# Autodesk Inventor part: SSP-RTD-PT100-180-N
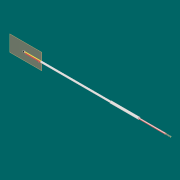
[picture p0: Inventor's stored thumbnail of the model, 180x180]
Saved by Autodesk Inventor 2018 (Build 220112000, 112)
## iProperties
Created: 2017-06
Part Number: SSP-RTD-PT100-180-N
Material: Generic
Document SubType Name: Modeling
Designer: JN
Density: 1 g/cm^3
Appearance: Smooth - Black
Author: JN
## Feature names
1. Extrusion1
2. Extrusion2
3. Extrusion3
4. Extrusion7
5. Extrusion8
6. Sweep1
7. Extrusion10
8. Loft8
9. Loft9
10. Loft10
11. Extrusion11
12. Extrusion12
13. Sweep5
14. Extrusion15
## Parameters: d0 = 50.8 mm, d1 = 25.4 mm, d2 = 0.0889 mm, d3 = 0, d4 = 2.54 mm, d5 = 2.286 mm, d6 = 2.032 mm, d7 = 1.016 mm, d8 = 0, d9 = 0.508 mm, d12 = 0.635 mm, d13 = 0, d14 = 0.9525 mm, d79 = 1.016 mm, d80 = 26.162 mm, d81 = 0, d82 = 1.016 mm, d84 = 26.162 mm, d85 = 0, d86 = -0.508 mm, d92 = 0, d93 = 0, d96 = 1.016 mm, d99 = 60 deg, d100 = 60 deg, d101 = 2.54 mm, d102 = 152.4 mm, d103 = 0, d104 = 1.016 mm, d105 = 0.508 mm, d108 = 1.016 mm, d109 = 1.016 mm, d110 = 44.45 mm, d111 = 1.016 mm, d112 = 1.016 mm, d113 = 1.016 mm, d114 = 0, d115 = 90 deg, d116 = 0, d117 = 90 deg, d118 = 0, d119 = 90 deg, d120 = 0, d121 = 90 deg, d122 = 0, d123 = 90 deg, d124 = 0, d125 = 90 deg, d126 = 0, d127 = 90 deg, d128 = 0, d129 = 90 deg, d130 = 0, d131 = 90 deg, d132 = 0.508 mm, d133 = 0.508 mm, d134 = 0.508 mm, d135 = 8.46667 mm, d136 = 0, d137 = 30 deg, d138 = 2.032 mm, d140 = 20.32 mm, d141 = 0, d142 = 1.016 mm, d148 = 0, d149 = 0, d155 = 0.9525 mm, d159 = 0.127 mm, d163 = 0.127 mm, d164 = 0.635 mm, d167 = 0.635 mm, d168 = -41.91 mm, d169 = 3.4798 mm, d170 = 44.45 mm, d171 = 0
